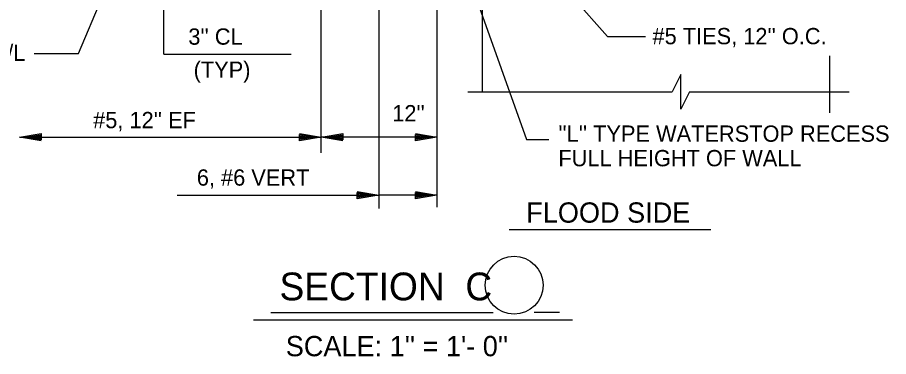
# Model space of a CAD drawing. Extents: x 22369.6 to 22428.3, y 22369.6 to 22415.
# Drawn here: x 22412.13 to 22422.16, y 22385.4 to 22389.3 of the extents above; entities that cross this region are included whole.
import ezdxf

# ---------------------------------------------------------------- set-up
doc = ezdxf.new("R2010")
doc.units = 0
for name, color, linetype in [('Level 1', 7, 'Continuous'), ('Level 10', 7, 'Continuous'), ('Level 2', 7, 'Continuous'), ('Level 3', 7, 'Continuous'), ('Level 4', 7, 'Continuous'), ('Level 7', 7, 'Continuous'), ('Level 8', 7, 'Continuous')]:
    doc.layers.add(name, color=color, linetype=linetype)

msp = doc.modelspace()

# ---------------------------------------------------------------- linework, layer by layer
at = {"layer": 'Level 1'}
for p, q in [((22416.287, 22392.235), (22416.287, 22387.105)), ((22416.958, 22392.22), (22416.958, 22387.12)), ((22415.625, 22387.745), (22415.625, 22391.568)), ((22417.067, 22391.197), (22418.922, 22389.082)), ((22413.811, 22388.879), (22413.811, 22390.447)), ((22417.223, 22390.05), (22417.991, 22387.899)), ((22412.832, 22388.886), (22413.206, 22389.78)), ((22418.922, 22389.082), (22419.359, 22389.082)), ((22412.318, 22388.886), (22412.832, 22388.886)), ((22413.811, 22388.879), (22415.278, 22388.879)), ((22421.483, 22388.204), (22421.483, 22388.862)), ((22417.315, 22388.447), (22419.666, 22388.447)), ((22419.865, 22388.447), (22421.703, 22388.447)), ((22412.15, 22387.925), (22415.625, 22387.925)), ((22415.532, 22387.925), (22415.532, 22387.925)), ((22416.958, 22387.925), (22415.625, 22387.925)), ((22415.625, 22387.925), (22415.625, 22387.925)), ((22415.625, 22387.925), (22415.625, 22387.925)), ((22415.696, 22387.925), (22415.696, 22387.925)), ((22415.717, 22387.925), (22415.717, 22387.925)), ((22416.865, 22387.925), (22416.865, 22387.925)), ((22416.958, 22387.925), (22416.958, 22387.925)), ((22417.991, 22387.899), (22418.246, 22387.899)), ((22413.966, 22387.258), (22416.287, 22387.258)), ((22416.958, 22387.258), (22416.287, 22387.258))]:
    msp.add_line(p, q, dxfattribs=at)
msp.add_lwpolyline([(22419.865, 22388.447), (22419.766, 22388.247), (22419.766, 22388.646), (22419.666, 22388.447)], dxfattribs=at)
at = {"layer": 'Level 10'}
for p, q in [((22417.79, 22386.863), (22420.113, 22386.863)), ((22415.045, 22385.906), (22417.604, 22385.906)), ((22418.369, 22385.906), (22418.077, 22385.906)), ((22414.845, 22385.823), (22418.517, 22385.823))]:
    msp.add_line(p, q, dxfattribs=at)
at = {"layer": 'Level 2'}
for points in [[(22412.4, 22387.883), (22412.15, 22387.925), (22412.4, 22387.966), (22412.4, 22387.895), (22412.22, 22387.925), (22412.389, 22387.953), (22412.389, 22387.907), (22412.286, 22387.925), (22412.378, 22387.939), (22412.378, 22387.921), (22412.356, 22387.925)], [(22415.375, 22387.966), (22415.625, 22387.925), (22415.375, 22387.883), (22415.375, 22387.954), (22415.555, 22387.925), (22415.386, 22387.897), (22415.386, 22387.942), (22415.489, 22387.925), (22415.397, 22387.91), (22415.397, 22387.929), (22415.419, 22387.925)], [(22415.874, 22387.883), (22415.625, 22387.925), (22415.874, 22387.966), (22415.874, 22387.895), (22415.694, 22387.925), (22415.863, 22387.953), (22415.863, 22387.907), (22415.761, 22387.925), (22415.853, 22387.939), (22415.853, 22387.921), (22415.83, 22387.925)], [(22416.709, 22387.966), (22416.958, 22387.925), (22416.709, 22387.883), (22416.709, 22387.954), (22416.889, 22387.925), (22416.719, 22387.897), (22416.719, 22387.942), (22416.822, 22387.925), (22416.73, 22387.91), (22416.73, 22387.929), (22416.753, 22387.925)], [(22416.038, 22387.299), (22416.287, 22387.258), (22416.038, 22387.217), (22416.038, 22387.287), (22416.218, 22387.258), (22416.049, 22387.23), (22416.049, 22387.275), (22416.151, 22387.258), (22416.059, 22387.243), (22416.059, 22387.262), (22416.082, 22387.258)], [(22416.709, 22387.299), (22416.958, 22387.258), (22416.709, 22387.217), (22416.709, 22387.287), (22416.889, 22387.258), (22416.719, 22387.23), (22416.719, 22387.275), (22416.822, 22387.258), (22416.73, 22387.243), (22416.73, 22387.262), (22416.753, 22387.258)]]:
    msp.add_lwpolyline(points, dxfattribs=at)
at = {"layer": 'Level 3'}
msp.add_circle((22417.847, 22386.221), 0.333, dxfattribs=at)
at = {"layer": 'Level 7'}
msp.add_line((22417.484, 22388.447), (22417.484, 22389.891), dxfattribs=at)
at = {"layer": 'Level 8'}
for p, q in [((22412.15, 22387.925), (22412.15, 22387.925)), ((22412.22, 22387.925), (22412.22, 22387.925)), ((22415.555, 22387.925), (22415.555, 22387.925)), ((22415.625, 22387.925), (22415.625, 22387.925)), ((22415.625, 22387.925), (22415.625, 22387.925)), ((22415.694, 22387.925), (22415.694, 22387.925)), ((22416.889, 22387.925), (22416.889, 22387.925)), ((22416.958, 22387.925), (22416.958, 22387.925)), ((22416.218, 22387.258), (22416.218, 22387.258)), ((22416.287, 22387.258), (22416.287, 22387.258)), ((22416.889, 22387.258), (22416.889, 22387.258)), ((22416.958, 22387.258), (22416.958, 22387.258))]:
    msp.add_line(p, q, dxfattribs=at)

# ---------------------------------------------------------------- texts
at = {"layer": 'Level 10'}
msp.add_text('FLOOD SIDE', height=0.2333, dxfattribs=at).set_placement((22417.986, 22386.941))
at = {"layer": 'Level 3'}
msp.add_text('SECTION  C', height=0.32, dxfattribs=at).set_placement((22415.145, 22386.047))
at = {"layer": 'Level 4'}
for s, p in [("3'' CL", (22414.095, 22388.989)), ("#5 TIES, 12'' O.C.", (22419.44, 22388.994)), ('W/L', (22411.772, 22388.802)), ('(TYP)', (22414.156, 22388.608)), ("12''", (22416.443, 22388.107)), ("#5, 12'' EF", (22412.999, 22388.028)), ("''L'' TYPE WATERSTOP RECESS", (22418.356, 22387.872)), ('FULL HEIGHT OF WALL', (22418.356, 22387.59)), ('6, #6 VERT', (22414.193, 22387.367))]:
    msp.add_text(s, height=0.1875, dxfattribs=at).set_placement(p)
at = {"layer": 'Level 7'}
msp.add_text("SCALE: 1'' = 1'- 0''", height=0.23333, dxfattribs=at).set_placement((22415.217, 22385.404))

doc.saveas('drawing.dxf')
